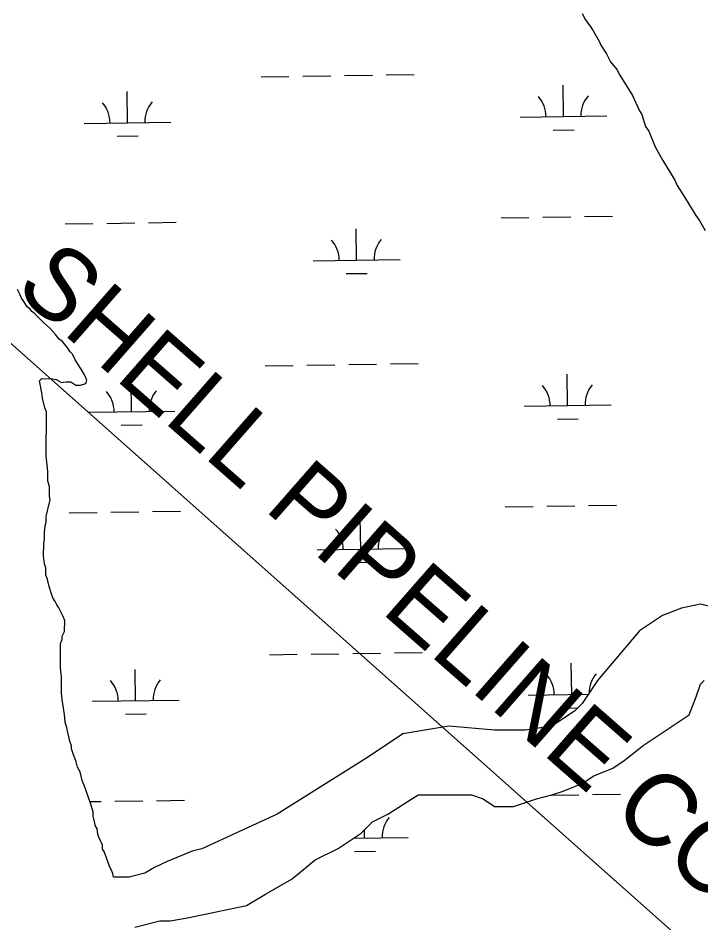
# Model space of a CAD drawing. Extents: x 3775218 to 3813389, y 343470 to 369318.
# Drawn here: x 3786941 to 3787727, y 361465 to 362507 of the extents above; entities that cross this region are included whole.
import ezdxf

# ---------------------------------------------------------------- set-up
doc = ezdxf.new("R2010")
doc.units = 0
for name, color, linetype in [('V-TOPO-SHOR', 7, 'Continuous'), ('V-UTIL-IDEN', 7, 'Continuous'), ('V-UTIL-LINE', 7, 'Continuous'), ('V-WETL-SWMP', 7, 'Continuous')]:
    doc.layers.add(name, color=color, linetype=linetype)

msp = doc.modelspace()

# ---------------------------------------------------------------- linework, layer by layer
at = {"layer": 'V-TOPO-SHOR'}
for p, q in [((3787590, 362511.9), (3787593.6, 362504.6)), ((3787593.6, 362504.6), (3787599.9, 362496.4)), ((3787599.9, 362496.4), (3787602.6, 362491.9)), ((3787602.6, 362491.9), (3787609.8, 362479.2)), ((3787609.8, 362479.2), (3787611.6, 362475.5)), ((3787611.6, 362475.5), (3787617.9, 362465.5)), ((3787617.9, 362465.5), (3787622.4, 362456.4)), ((3787622.4, 362456.4), (3787629.7, 362447.4)), ((3787629.7, 362447.4), (3787633.3, 362441)), ((3787633.3, 362441), (3787647.7, 362417.4)), ((3787647.7, 362417.4), (3787655.8, 362400.1)), ((3787655.8, 362400.1), (3787658.5, 362395.6)), ((3787658.5, 362395.6), (3787663, 362381.9)), ((3787663, 362381.9), (3787666.6, 362376.5)), ((3787666.6, 362376.5), (3787673.8, 362358.3)), ((3787673.8, 362358.3), (3787682.8, 362342.9)), ((3787682.8, 362342.9), (3787696.4, 362320.2)), ((3787696.4, 362320.2), (3787699.1, 362313.8)), ((3787699.1, 362313.8), (3787708.1, 362300.2)), ((3787708.1, 362300.2), (3787720.7, 362279.3)), ((3787720.7, 362279.3), (3787725.3, 362272.9)), ((3787725.3, 362272.9), (3787731.6, 362262)), ((3786942.9, 362188.8), (3786940.2, 362194.2)), ((3786944.7, 362184.3), (3786942.9, 362188.8)), ((3786946.6, 362181.5), (3786944.7, 362184.3)), ((3786951.1, 362174.3), (3786946.6, 362181.5)), ((3786954.7, 362171.5), (3786951.1, 362174.3)), ((3786956.5, 362168.8), (3786954.7, 362171.5)), ((3786959.2, 362167), (3786956.5, 362168.8)), ((3786970.1, 362156.1), (3786959.2, 362167)), ((3786977.3, 362149.7), (3786970.1, 362156.1)), ((3786983.6, 362142.4), (3786977.3, 362149.7)), ((3786988.1, 362136.9), (3786983.6, 362142.4)), ((3786991.8, 362134.2), (3786988.1, 362136.9)), ((3786998.1, 362126.9), (3786991.8, 362134.2)), ((3787000.8, 362122.4), (3786998.1, 362126.9)), ((3787003.5, 362119.7), (3787000.8, 362122.4)), ((3787006.2, 362114.2), (3787003.5, 362119.7)), ((3787009.8, 362107.9), (3787006.2, 362114.2)), ((3787013.4, 362102.4), (3787009.8, 362107.9)), ((3787017, 362096), (3787013.4, 362102.4)), ((3786965.3, 362089), (3786968, 362091.7)), ((3786968, 362075.3), (3786965.3, 362089)), ((3786968, 362091.7), (3786980.7, 362091.6)), ((3786980.7, 362091.6), (3786984.4, 362090.7)), ((3786984.4, 362090.7), (3786988, 362088.9)), ((3786988, 362088.9), (3786990.7, 362087.1)), ((3787019.7, 362089.7), (3787017, 362096)), ((3787018.8, 362086.1), (3787019.7, 362089.7)), ((3786990.7, 362087.1), (3786996.1, 362087.9)), ((3786996.1, 362087.9), (3787001.6, 362087.9)), ((3787001.6, 362087.9), (3787007, 362084.3)), ((3787007, 362084.3), (3787012.5, 362084.3)), ((3787012.5, 362084.3), (3787018.8, 362086.1)), ((3786968.9, 362069), (3786968, 362075.3)), ((3786971.6, 362058.1), (3786968.9, 362069)), ((3786973.4, 362053.6), (3786971.6, 362058.1)), ((3786973.2, 362002.8), (3786973.4, 362053.6)), ((3786974.1, 361991.9), (3786973.2, 362002.8)), ((3786975, 361984.6), (3786974.1, 361991.9)), ((3786974.9, 361973.7), (3786975, 361984.6)), ((3786976.7, 361967.4), (3786974.9, 361973.7)), ((3786976.7, 361956.5), (3786976.7, 361967.4)), ((3786977.6, 361952), (3786976.7, 361956.5)), ((3786973, 361932.9), (3786976.6, 361947.4)), ((3786976.6, 361947.4), (3786977.6, 361952)), ((3786973, 361926.6), (3786973, 361932.9)), ((3786971.1, 361914.8), (3786972, 361922)), ((3786972, 361922), (3786973, 361926.6)), ((3786971.1, 361907.5), (3786971.1, 361914.8)), ((3786970.1, 361887.6), (3786970.2, 361901.2)), ((3786970.2, 361901.2), (3786971.1, 361907.5)), ((3786971, 361878.5), (3786970.1, 361887.6)), ((3786972.8, 361874), (3786971, 361878.5)), ((3786972.8, 361865.8), (3786972.8, 361874)), ((3786974.6, 361860.4), (3786972.8, 361865.8)), ((3786976.3, 361852.2), (3786974.6, 361860.4)), ((3786979, 361844), (3786976.3, 361852.2)), ((3786980.8, 361839.5), (3786979, 361844)), ((3786983.5, 361834.9), (3786980.8, 361839.5)), ((3786985.4, 361831.3), (3786983.5, 361834.9)), ((3786987.2, 361828.6), (3786985.4, 361831.3)), ((3786991.7, 361819.5), (3786987.2, 361828.6)), ((3787726.1, 361832), (3787704.2, 361827.6)), ((3787761.2, 361823.2), (3787726.1, 361832)), ((3786994.4, 361813.1), (3786991.7, 361819.5)), ((3787682.2, 361818.8), (3787655.9, 361801.3)), ((3787704.2, 361827.6), (3787682.2, 361818.8)), ((3786994.3, 361800.4), (3786994.4, 361813.1)), ((3786991.6, 361795), (3786994.3, 361800.4)), ((3787655.9, 361801.3), (3787607.6, 361744.2)), ((3786989.7, 361786.8), (3786991.6, 361791.4)), ((3786989.7, 361757.8), (3786989.7, 361786.8)), ((3786991.6, 361791.4), (3786991.6, 361795)), ((3786990.5, 361748.7), (3786989.7, 361757.8)), ((3786990.5, 361729.7), (3786990.5, 361748.7)), ((3787607.6, 361744.2), (3787590, 361717.8)), ((3786991.4, 361722.4), (3786990.5, 361729.7)), ((3786994, 361705.2), (3786991.4, 361722.4)), ((3787590, 361717.8), (3787581.2, 361709)), ((3786994.9, 361696.1), (3786994, 361705.2)), ((3787581.2, 361709), (3787554.9, 361691.4)), ((3786996.7, 361689.8), (3786994.9, 361696.1)), ((3787000.3, 361674.3), (3786996.7, 361689.8)), ((3787383.7, 361682.7), (3787344.2, 361656.3)), ((3787436.3, 361691.4), (3787383.7, 361682.7)), ((3787489, 361687), (3787436.3, 361691.4)), ((3787524.2, 361687), (3787489, 361687)), ((3787554.9, 361691.4), (3787524.2, 361687)), ((3787002.1, 361668.9), (3787000.3, 361674.3)), ((3787002.1, 361665.3), (3787002.1, 361668.9)), ((3787003.9, 361660.7), (3787002.1, 361665.3)), ((3787007.5, 361650.7), (3787003.9, 361660.7)), ((3787344.2, 361656.3), (3787238.8, 361590.4)), ((3787009.2, 361644.4), (3787007.5, 361650.7)), ((3787012, 361638.9), (3787009.2, 361644.4)), ((3787014.6, 361628.9), (3787012, 361638.9)), ((3787017.3, 361622.6), (3787014.6, 361628.9)), ((3787019.1, 361617.1), (3787017.3, 361622.6)), ((3787024.5, 361601.7), (3787019.1, 361617.1)), ((3787027.2, 361592.6), (3787024.5, 361601.7)), ((3787027.2, 361588.1), (3787027.2, 361592.6)), ((3787238.8, 361590.4), (3787152.1, 361550.3)), ((3787029, 361579.9), (3787027.2, 361588.1)), ((3787029.9, 361576.3), (3787029, 361579.9)), ((3787031.7, 361573.6), (3787029.9, 361576.3)), ((3787032.6, 361567.2), (3787031.7, 361573.6)), ((3787033.5, 361563.6), (3787032.6, 361567.2)), ((3787035.3, 361560.9), (3787033.5, 361563.6)), ((3787038, 361554.5), (3787035.3, 361560.9)), ((3787038, 361550), (3787038, 361554.5)), ((3787039.8, 361547.2), (3787038, 361550)), ((3787042.5, 361540), (3787039.8, 361547.2)), ((3787141.2, 361547.6), (3787112.2, 361535.9)), ((3787152.1, 361550.3), (3787141.2, 361547.6)), ((3787044.3, 361534.5), (3787042.5, 361540)), ((3787046.1, 361530), (3787044.3, 361534.5)), ((3787047.9, 361526.4), (3787046.1, 361530)), ((3787049.7, 361521.8), (3787047.9, 361526.4)), ((3787097.6, 361528.7), (3787086.7, 361522.3)), ((3787112.2, 361535.9), (3787097.6, 361528.7)), ((3787050.5, 361517.9), (3787049.7, 361521.8)), ((3787068.6, 361517.9), (3787050.5, 361517.9)), ((3787086.7, 361522.3), (3787068.6, 361517.9))]:
    msp.add_line(p, q, dxfattribs=at)
for points in [[(3787511, 361599.2), (3787537.3, 361608), (3787554.9, 361612.4), (3787568.1, 361616.8), (3787590, 361625.5), (3787603.2, 361634.3), (3787625.1, 361643.1), (3787638.3, 361651.9), (3787660.3, 361669.5), (3787712.9, 361704.6), (3787721.7, 361726.6), (3787726.1, 361739.8), (3787730.5, 361744.2)], [(3787075, 361460.1), (3787104, 361467.3), (3787115.8, 361467.3), (3787135.8, 361470.8), (3787203.7, 361485), (3787225.6, 361498.1), (3787256.3, 361515.7), (3787282.7, 361537.7), (3787309, 361550.9), (3787335.4, 361568.4), (3787348.5, 361581.6), (3787366.1, 361590.4), (3787401.2, 361612.4), (3787462.7, 361612.4), (3787475.9, 361608), (3787489, 361599.2), (3787511, 361599.2)]]:
    msp.add_lwpolyline(points, dxfattribs=at)
at = {"layer": 'V-UTIL-LINE'}
msp.add_lwpolyline([(3780679.3, 367094), (3785426.9, 363471.2), (3792974.2, 356758.7), (3793366, 356995.9), (3793845.8, 357258.7), (3797110.8, 352684.9), (3797510.2, 352064.7), (3798847.9, 350037.3), (3800878.7, 349194.8)], dxfattribs=at)
at = {"layer": 'V-WETL-SWMP'}
for p, q in [((3787220.5, 362439.1), (3787252.5, 362439.6)), ((3787268.5, 362439.8), (3787300.5, 362440.3)), ((3787316.5, 362440.5), (3787348.5, 362440.9)), ((3787364.5, 362441.2), (3787396.5, 362441.6)), ((3787066.6, 362386.2), (3787066.1, 362422.2)), ((3787568.5, 362393.3), (3787568, 362429.3)), ((3787518.5, 362392.6), (3787618.5, 362394)), ((3787016.6, 362385.5), (3787116.6, 362386.9)), ((3787054.9, 362370.6), (3787078.9, 362371)), ((3787556.7, 362377.7), (3787580.7, 362378)), ((3787496.7, 362276.8), (3787528.7, 362277.3)), ((3787544.7, 362277.5), (3787576.7, 362278)), ((3787592.7, 362278.2), (3787624.7, 362278.6)), ((3786994.9, 362269.8), (3787026.9, 362270.2)), ((3787042.9, 362270.4), (3787074.9, 362270.9)), ((3787090.9, 362271.1), (3787122.8, 362271.6)), ((3787330.3, 362228.1), (3787329.8, 362264)), ((3787280.3, 362227.3), (3787380.3, 362228.8)), ((3787318.5, 362212.5), (3787342.5, 362212.8)), ((3787225.2, 362106.5), (3787257.2, 362106.9)), ((3787273.2, 362107.2), (3787305.2, 362107.6)), ((3787321.2, 362107.8), (3787353.2, 362108.3)), ((3787369.2, 362108.5), (3787401.2, 362109)), ((3787071.3, 362053.6), (3787070.8, 362089.6)), ((3787573.2, 362060.6), (3787572.7, 362096.6)), ((3787523.2, 362059.9), (3787623.2, 362061.4)), ((3787021.3, 362052.9), (3787121.3, 362054.3)), ((3787059.5, 362038), (3787083.5, 362038.3)), ((3787561.4, 362045.1), (3787585.4, 362045.4)), ((3787501.4, 361944.2), (3787533.4, 361944.6)), ((3787549.4, 361944.9), (3787581.4, 361945.3)), ((3787597.4, 361945.5), (3787629.4, 361946)), ((3786999.6, 361937.1), (3787031.6, 361937.6)), ((3787047.6, 361937.8), (3787079.5, 361938.2)), ((3787095.5, 361938.5), (3787127.5, 361938.9)), ((3787335, 361895.4), (3787334.5, 361931.4)), ((3787285, 361894.7), (3787385, 361896.1)), ((3787323.2, 361879.8), (3787347.2, 361880.2)), ((3787373.9, 361775.9), (3787405.9, 361776.3)), ((3787229.9, 361773.8), (3787261.9, 361774.3)), ((3787277.9, 361774.5), (3787309.9, 361775)), ((3787325.9, 361775.2), (3787357.9, 361775.7)), ((3787076, 361720.9), (3787075.5, 361756.9)), ((3787577.9, 361728), (3787577.4, 361764)), ((3787527.9, 361727.3), (3787597, 361728.3)), ((3787026, 361720.2), (3787126, 361721.6)), ((3787064.2, 361705.3), (3787088.2, 361705.7)), ((3787566.1, 361712.4), (3787584.9, 361712.7)), ((3787554.4, 361612.2), (3787586, 361612.7)), ((3787602, 361612.9), (3787634, 361613.4)), ((3787023.5, 361604.7), (3787036.2, 361604.9)), ((3787052.2, 361605.1), (3787084.2, 361605.6)), ((3787100.2, 361605.8), (3787132.2, 361606.3)), ((3787339.6, 361562.8), (3787339.5, 361572.6)), ((3787326.6, 361562.6), (3787389.6, 361563.5)), ((3787327.9, 361547.2), (3787351.9, 361547.5))]:
    msp.add_line(p, q, dxfattribs=at)
for points in [[(3787590, 362511.9), (3787593.6, 362504.6), (3787599.9, 362496.4), (3787602.6, 362491.9), (3787609.8, 362479.2), (3787611.6, 362475.5), (3787617.9, 362465.5), (3787622.4, 362456.4), (3787629.7, 362447.4), (3787633.3, 362441), (3787647.7, 362417.4), (3787655.8, 362400.1), (3787658.5, 362395.6), (3787663, 362381.9), (3787666.6, 362376.5), (3787673.8, 362358.3), (3787682.8, 362342.9), (3787696.4, 362320.2), (3787699.1, 362313.8), (3787708.1, 362300.2), (3787720.7, 362279.3), (3787725.3, 362272.9), (3787731.6, 362262)], [(3786980.7, 362091.6), (3786984.4, 362090.7), (3786988, 362088.9), (3786990.7, 362087.1), (3786996.1, 362087.9), (3787001.6, 362087.9), (3787007, 362084.3), (3787012.5, 362084.3), (3787018.8, 362086.1), (3787019.7, 362089.7), (3787017, 362096), (3787013.4, 362102.4), (3787009.8, 362107.9), (3787006.2, 362114.2), (3787003.5, 362119.7), (3787000.8, 362122.4), (3786998.1, 362126.9), (3786991.8, 362134.2), (3786988.1, 362136.9), (3786983.6, 362142.4), (3786977.3, 362149.7), (3786970.1, 362156.1), (3786959.2, 362167), (3786956.5, 362168.8), (3786954.7, 362171.5), (3786951.1, 362174.3), (3786946.6, 362181.5), (3786944.7, 362184.3), (3786942.9, 362188.8), (3786940.2, 362194.2)], [(3787554.9, 361691.4), (3787524.2, 361687), (3787489, 361687), (3787436.4, 361691.4), (3787383.7, 361682.7), (3787344.2, 361656.3), (3787238.8, 361590.4), (3787152.1, 361550.3), (3787141.2, 361547.6), (3787112.2, 361535.9), (3787097.6, 361528.7), (3787086.7, 361522.3), (3787068.6, 361517.9), (3787050.5, 361517.9), (3787049.7, 361521.8), (3787047.9, 361526.4), (3787046.1, 361530), (3787044.3, 361534.5), (3787042.5, 361540), (3787039.8, 361547.2), (3787038, 361550), (3787038, 361554.5), (3787035.3, 361560.9), (3787033.5, 361563.6), (3787032.6, 361567.2), (3787031.7, 361573.6), (3787029.9, 361576.3), (3787029, 361579.9), (3787027.2, 361588.1), (3787027.2, 361592.6), (3787024.5, 361601.7), (3787019.1, 361617.1), (3787017.3, 361622.6), (3787014.6, 361628.9), (3787012, 361638.9), (3787009.2, 361644.4), (3787007.5, 361650.7), (3787003.9, 361660.7), (3787002.1, 361665.3), (3787002.1, 361668.9), (3787000.3, 361674.3), (3786996.7, 361689.8), (3786994.9, 361696.1), (3786994, 361705.2), (3786991.4, 361722.4), (3786990.5, 361729.7), (3786990.5, 361748.7), (3786989.7, 361757.8), (3786989.7, 361786.8), (3786991.6, 361791.4), (3786991.6, 361795), (3786994.3, 361800.4), (3786994.4, 361813.1), (3786991.7, 361819.5), (3786987.2, 361828.6), (3786985.4, 361831.3), (3786983.5, 361834.9), (3786980.8, 361839.5), (3786979, 361844), (3786976.3, 361852.2), (3786974.6, 361860.4), (3786972.8, 361865.8), (3786972.8, 361874), (3786971, 361878.5), (3786970.1, 361887.6), (3786970.2, 361901.2), (3786971.1, 361907.5), (3786971.1, 361914.8), (3786972, 361922), (3786973, 361926.6), (3786973, 361932.9), (3786976.6, 361947.4), (3786977.6, 361952), (3786976.7, 361956.5), (3786976.7, 361967.4), (3786974.9, 361973.7), (3786975, 361984.6), (3786974.1, 361991.9), (3786973.2, 362002.8), (3786973.4, 362053.6), (3786971.6, 362058.1), (3786968.9, 362069), (3786968, 362075.3), (3786965.3, 362089), (3786968, 362091.7), (3786980.7, 362091.6)], [(3787761.2, 361823.2), (3787726.1, 361832), (3787704.2, 361827.6), (3787682.2, 361818.8), (3787655.9, 361801.3), (3787607.6, 361744.2), (3787590, 361717.8), (3787581.2, 361709), (3787554.9, 361691.4)], [(3787511, 361599.2), (3787537.3, 361608), (3787554.9, 361612.4), (3787568.1, 361616.8), (3787590, 361625.5), (3787603.2, 361634.3), (3787625.1, 361643.1), (3787638.3, 361651.9), (3787660.3, 361669.5), (3787712.9, 361704.6), (3787721.7, 361726.6), (3787726.1, 361739.8), (3787730.5, 361744.2)], [(3787075, 361460.1), (3787104, 361467.3), (3787115.8, 361467.3), (3787135.8, 361470.8), (3787203.7, 361485), (3787225.6, 361498.1), (3787256.3, 361515.7), (3787282.7, 361537.7), (3787309, 361550.9), (3787335.4, 361568.4), (3787348.5, 361581.6), (3787366.1, 361590.4), (3787401.2, 361612.4), (3787462.7, 361612.4), (3787475.9, 361608), (3787489, 361599.2), (3787511, 361599.2)]]:
    msp.add_lwpolyline(points, dxfattribs=at)
for centre, start, end in [((3787513.2, 362393), 0.0365, 41.5802), ((3787623.7, 362394.5), 140.0365, 181.5802), ((3787011.4, 362385.9), 0.0365, 41.5802), ((3787121.9, 362387.5), 140.0365, 181.5802), ((3787275.1, 362227.7), 0.0365, 41.5802), ((3787385.6, 362229.3), 140.0365, 181.5802), ((3787517.9, 362060.3), 0.0365, 41.5802), ((3787628.4, 362061.9), 140.0365, 181.5802), ((3787016.1, 362053.3), 0.0365, 41.5802), ((3787126.6, 362054.8), 140.0365, 181.5802), ((3787279.8, 361895.1), 0.0365, 41.5802), ((3787390.3, 361896.7), 140.0365, 181.5802), ((3787131.3, 361722.2), 140.0365, 181.5802), ((3787522.6, 361727.7), 0.0365, 41.5802), ((3787633.1, 361729.3), 140.0365, 179.4717), ((3787020.8, 361720.6), 0.0365, 41.5802), ((3787394.9, 361564), 140.0365, 181.5802)]:
    msp.add_arc(centre, 35.2, start, end, dxfattribs=at)

# ---------------------------------------------------------------- texts
at = {"layer": 'V-UTIL-IDEN'}
msp.add_text('SHELL PIPELINE CO. ', height=83, rotation=318.7588, dxfattribs=at).set_placement((3786934.9, 362193.6))

doc.saveas('drawing.dxf')
